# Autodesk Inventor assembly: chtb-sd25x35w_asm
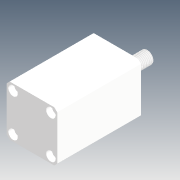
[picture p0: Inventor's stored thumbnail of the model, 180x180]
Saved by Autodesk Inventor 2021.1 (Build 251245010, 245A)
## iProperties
Company: Microsoft
Created: 2018-05
Part Number: chtb-sd25x35w_asm
Description: STEP AP214
Document SubType Name: Assembly
Designer: user
Title: chtb-sd25x35w_asm.STEP
Author: Windows
Revision Number: ÈÎºÎ
Sending System: SolidWorks 2015
Preprocessor: SwSTEP 2.0
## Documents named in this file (4)
- D:\Vault_2016\Projekty\Clamptek\Hydraulic\CHTB\CHTB-25\Inventor\chtb-sd25x35w\chtb-sd25x35w_asm.iam
- D:\Vault_2016\Projekty\Clamptek\Hydraulic\CHTB\CHTB-25\Inventor\chtb-sd25x35w\CHTB-25QG.ipt
- D:\Vault_2016\Projekty\Clamptek\Hydraulic\CHTB\CHTB-25\Inventor\chtb-sd25x35w\CHTB-SD25X35NBT.ipt
- D:\Vault_2016\Projekty\Clamptek\Hydraulic\CHTB\CHTB-25\Inventor\chtb-sd25x35w\CHTB-SD25X35WHSG.ipt
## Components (3 placed, 3 different names)
1. CHTB-25QG_1
2. CHTB-SD25X35NBT_2
3. CHTB-SD25X35WHSG_3
